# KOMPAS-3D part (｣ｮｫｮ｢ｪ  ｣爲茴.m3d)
File: created 24.10.2015 22:02:07, last saved 06.02.2016 14:02:04.
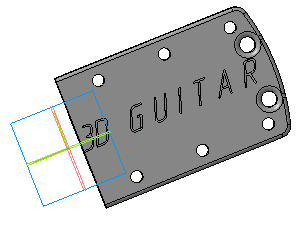
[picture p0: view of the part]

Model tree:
1. Эскиз:1
2. Операция выдавливания:1
     Расстояние 1 = 16
3. Эскиз:2
4. Вырезать элемент выдавливания:1
     Расстояние 1 = 14.4
5. Эскиз:3
6. Операция выдавливания:2
     Расстояние 1 = 2; Расстояние 2 = 124
7. Скругление:1
     Радиус = 5
8. Скругление:2
     Радиус = 5
9. Скругление:3
     Радиус = 5
10. Эскиз:4
11. Операция выдавливания:3
     Расстояние 1 = 5; Расстояние 2 = 115
12. Эскиз:5
13. Эскиз:6
14. Операция выдавливания:4
     Расстояние 1 = 2
15. Скругление:4
     Радиус = 3
16. Эскиз:7
17. Операция выдавливания:5
     Расстояние 1 = 0.5
18. Эскиз:8
19. Вырезать элемент выдавливания:2
     Расстояние 1 = 30
20. Эскиз:9
21. Вырезать элемент выдавливания:3
     Расстояние 1 = 30
22. Скругление:5
     Радиус = 3
23. Скругление:6
     Радиус = 7
24. Скругление:7
     Радиус = 2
